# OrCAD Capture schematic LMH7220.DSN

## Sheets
1 Top_Block: size A
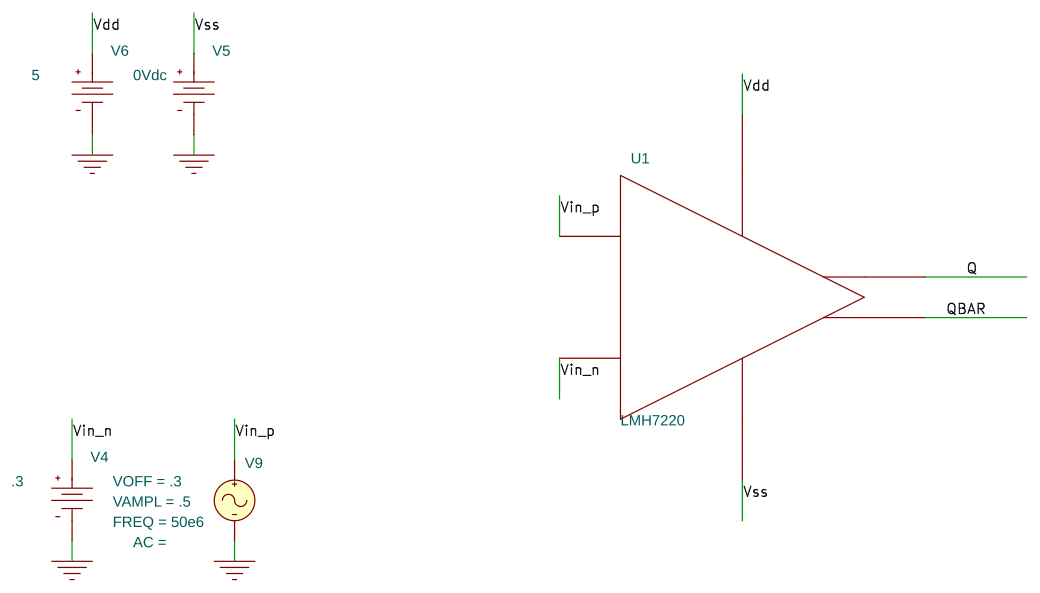
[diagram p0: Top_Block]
2 Top
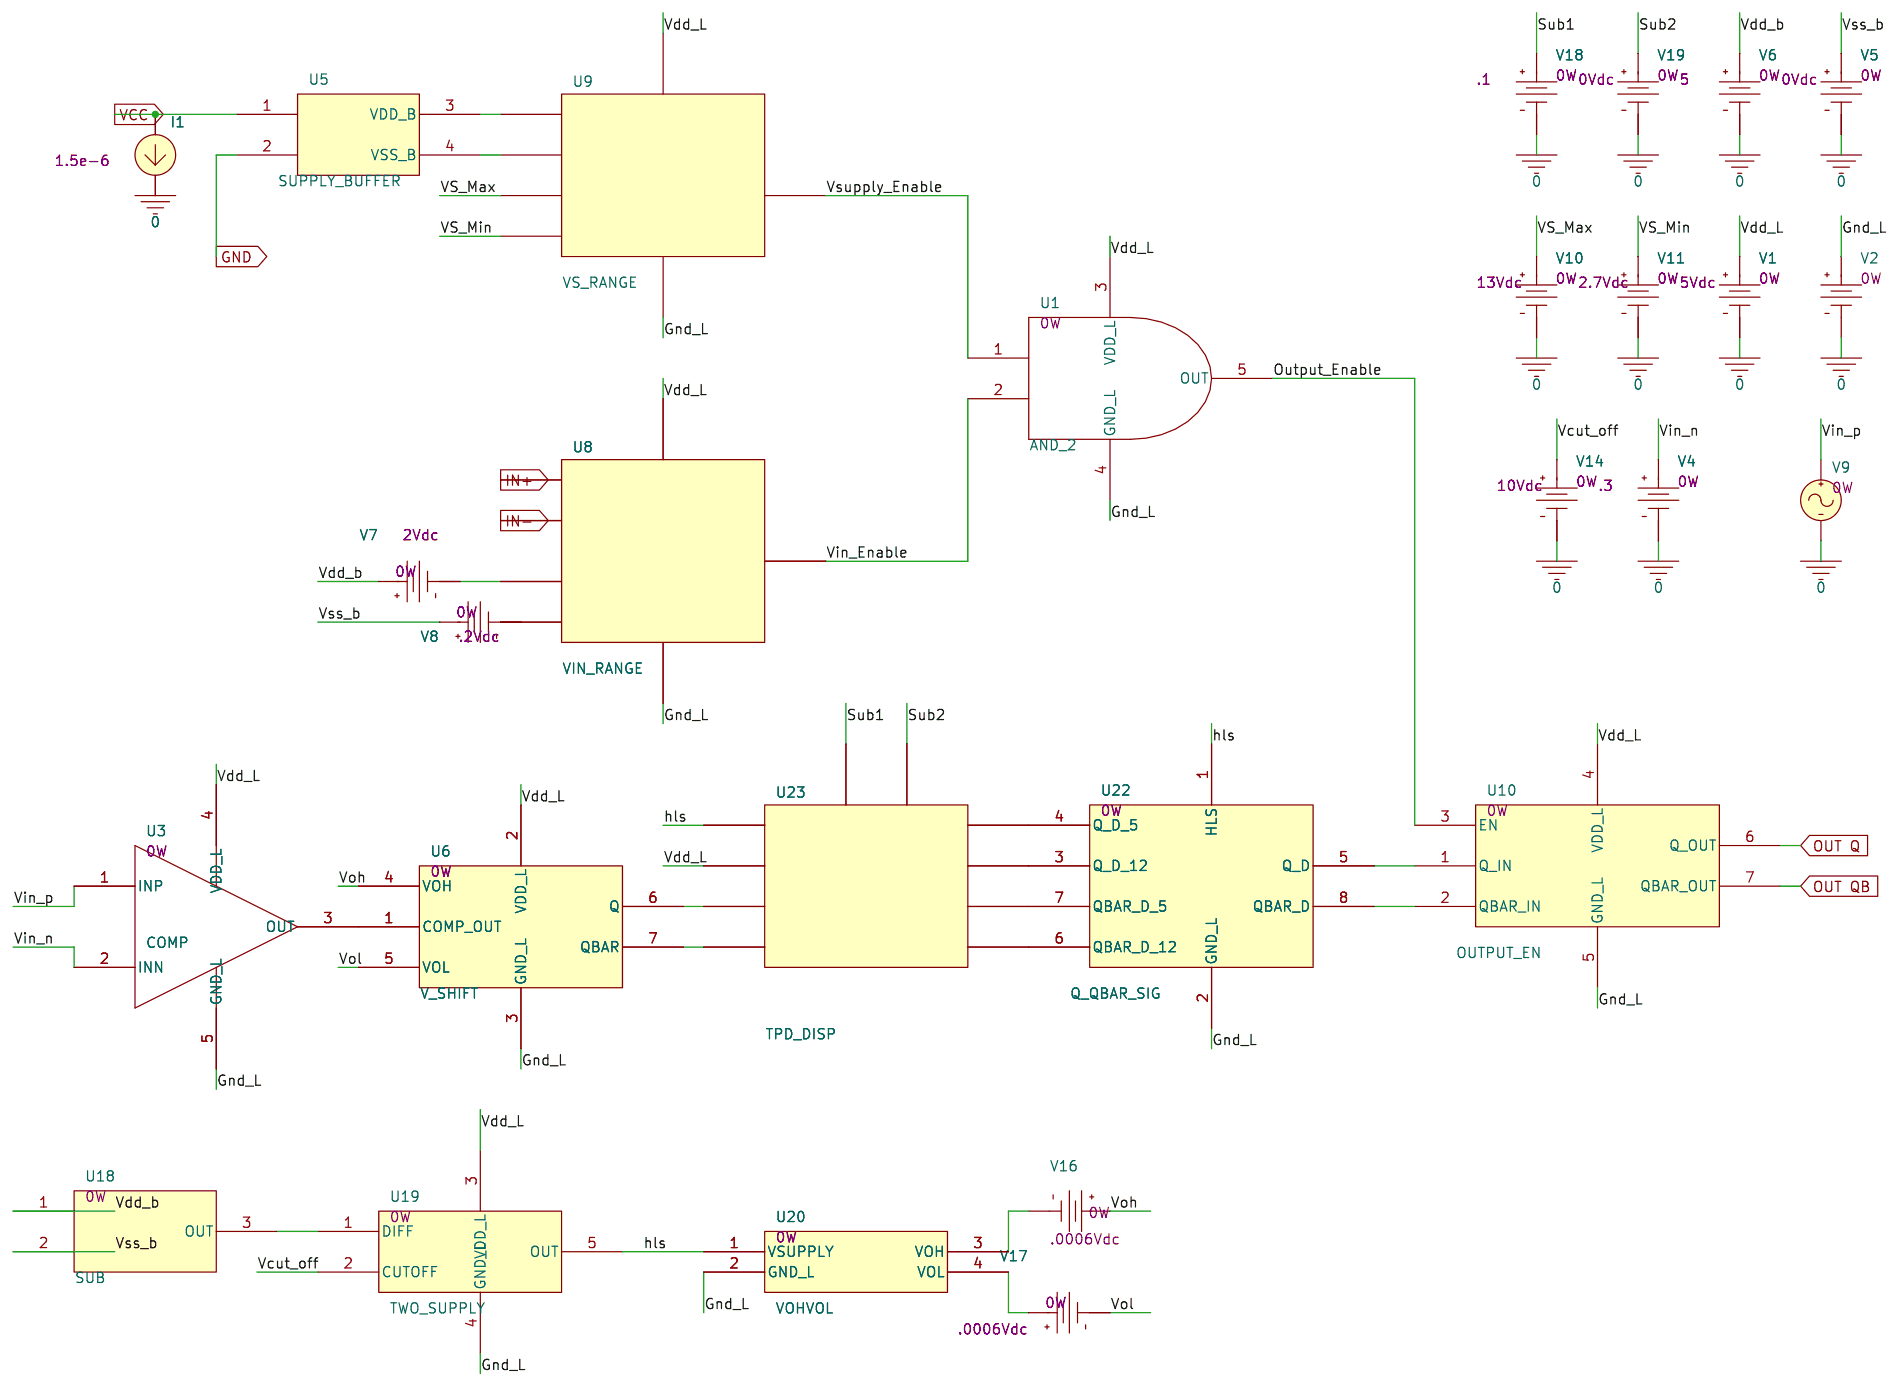
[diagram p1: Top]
3 PAGE2
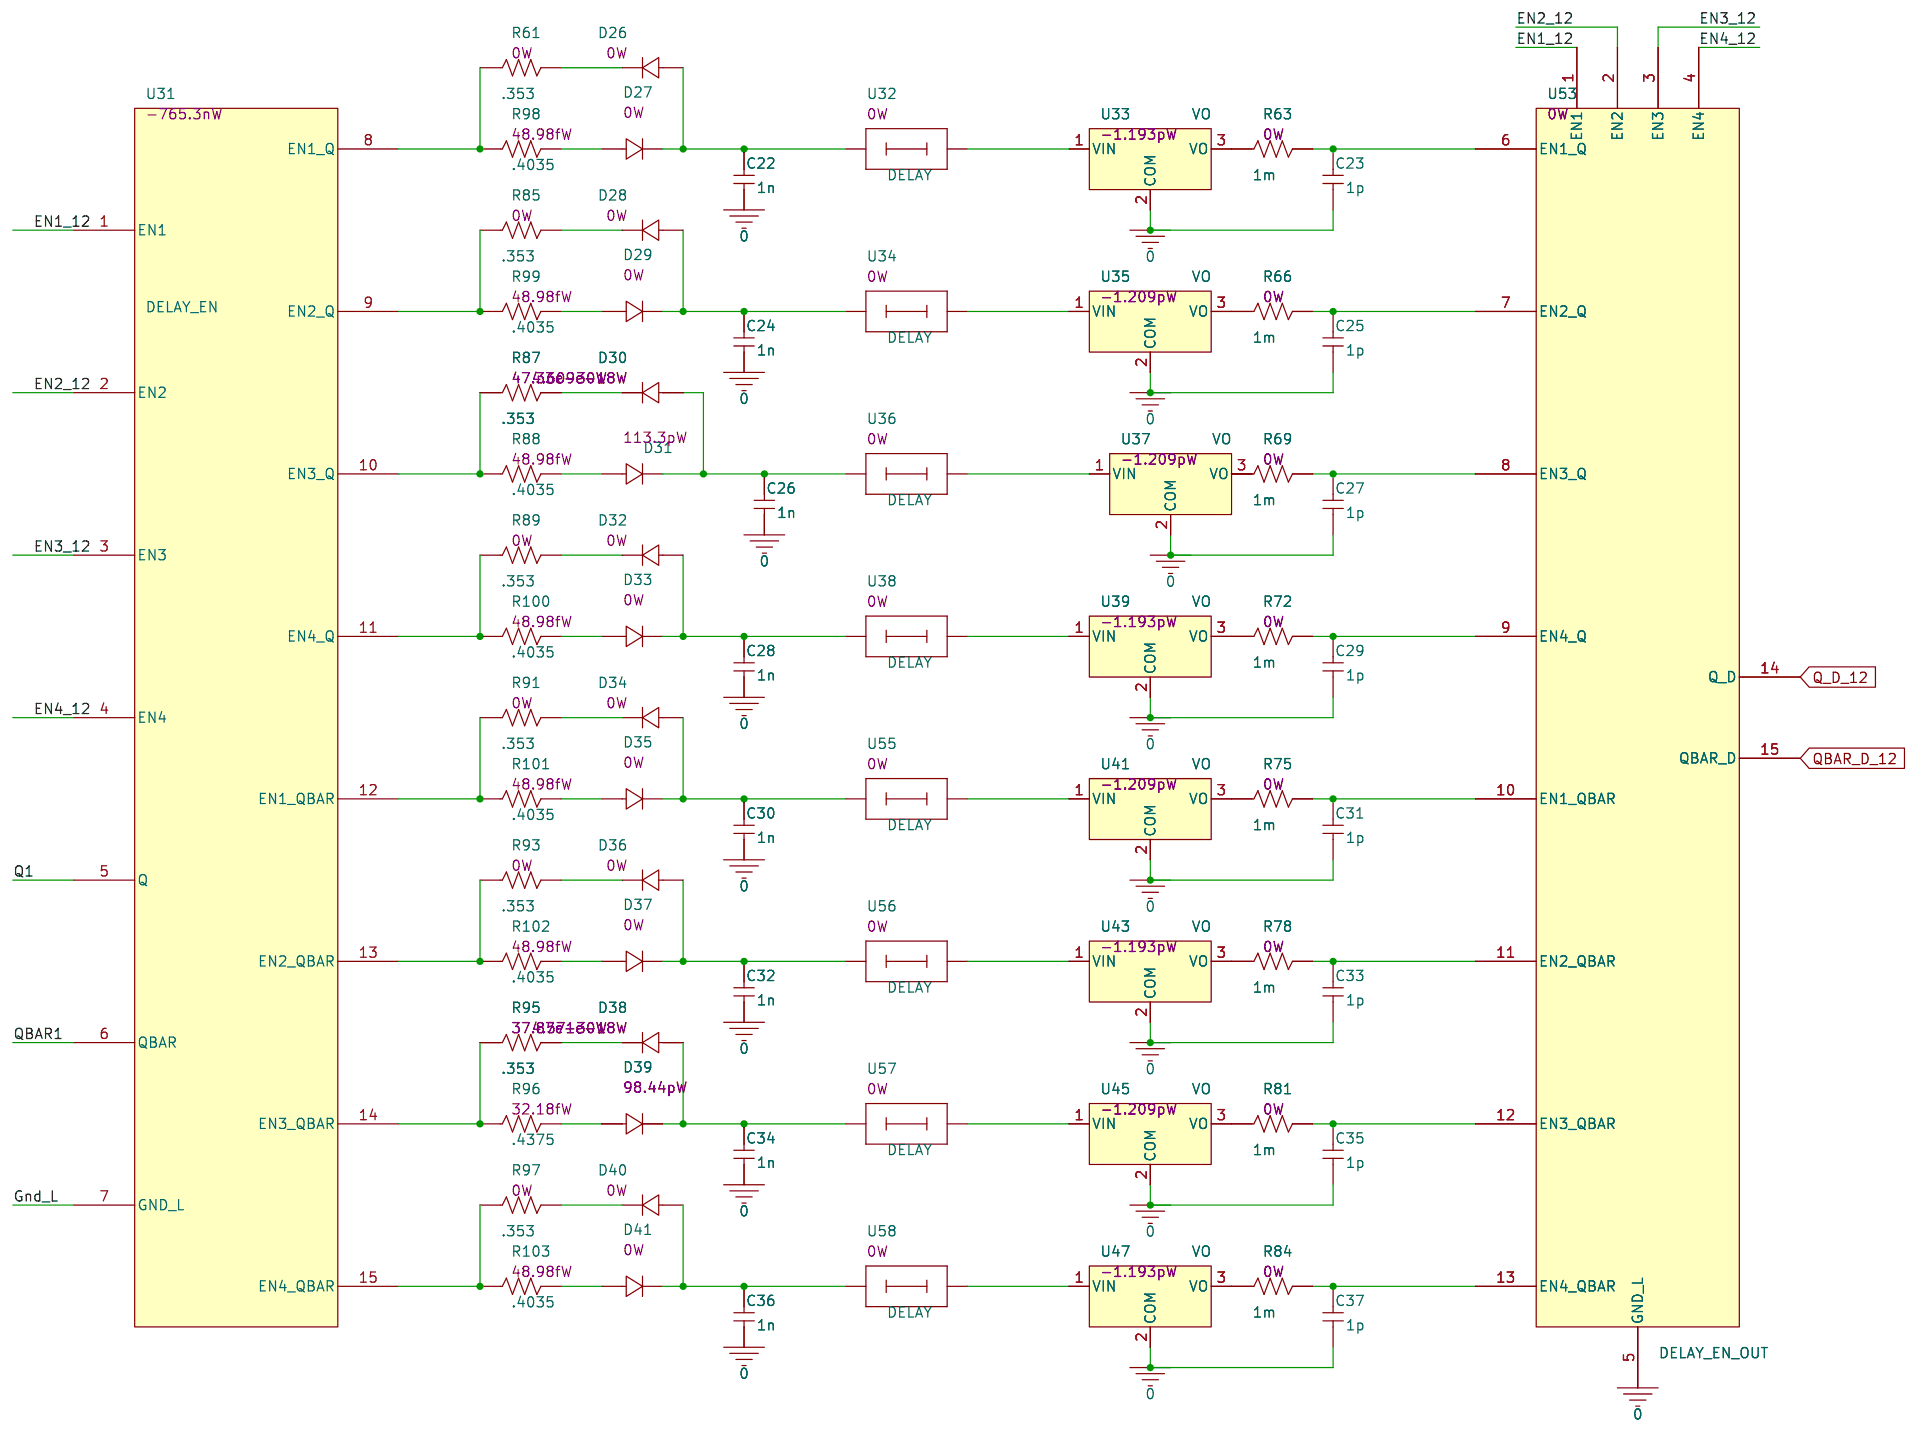
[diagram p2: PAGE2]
4 PAGE1
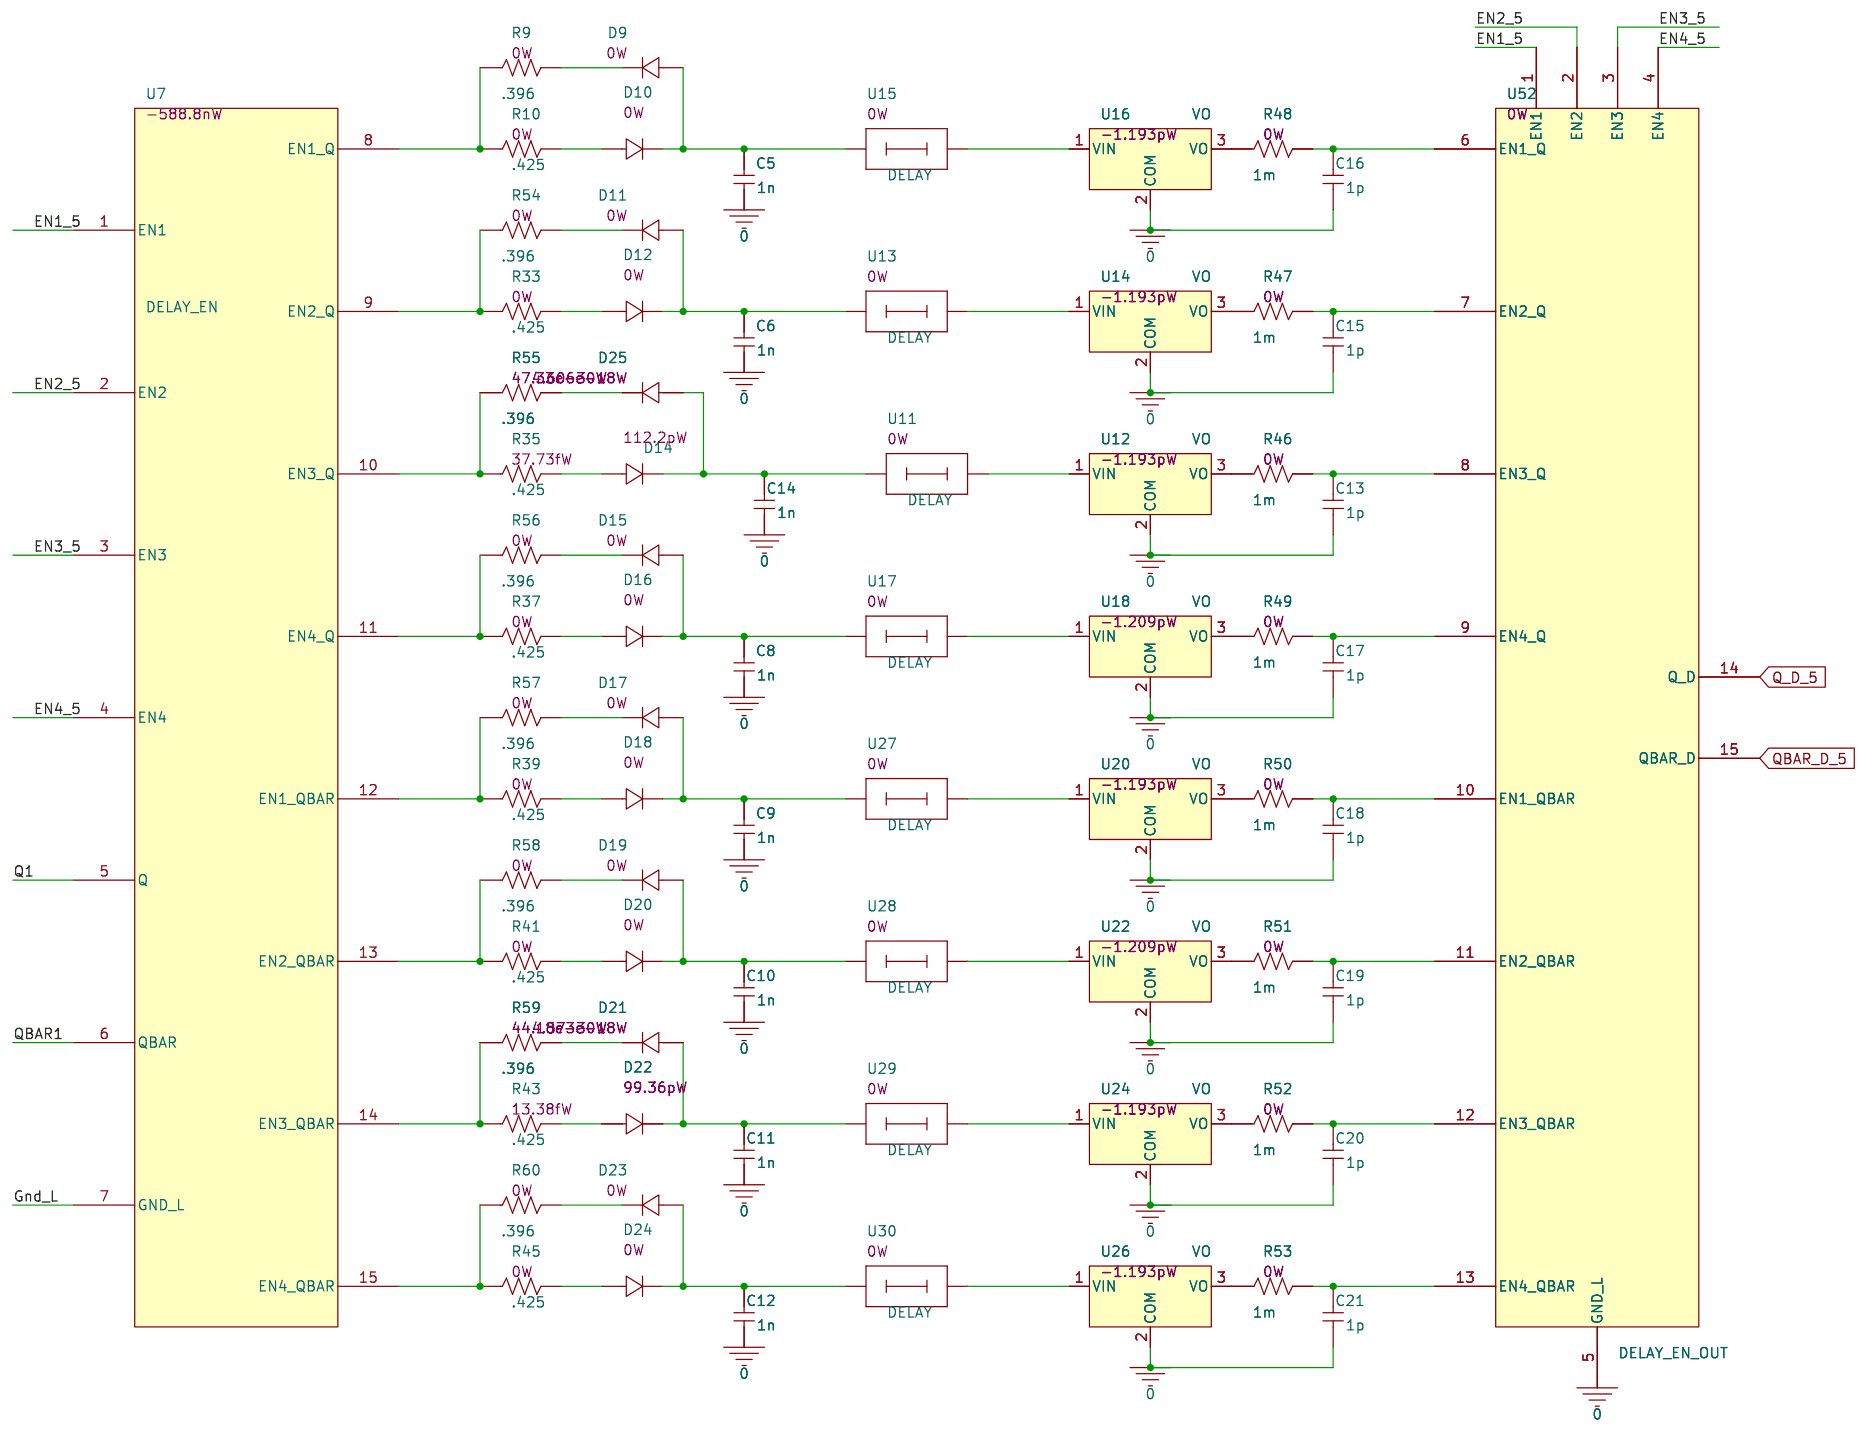
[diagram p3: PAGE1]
5 Tpd_Dispersion
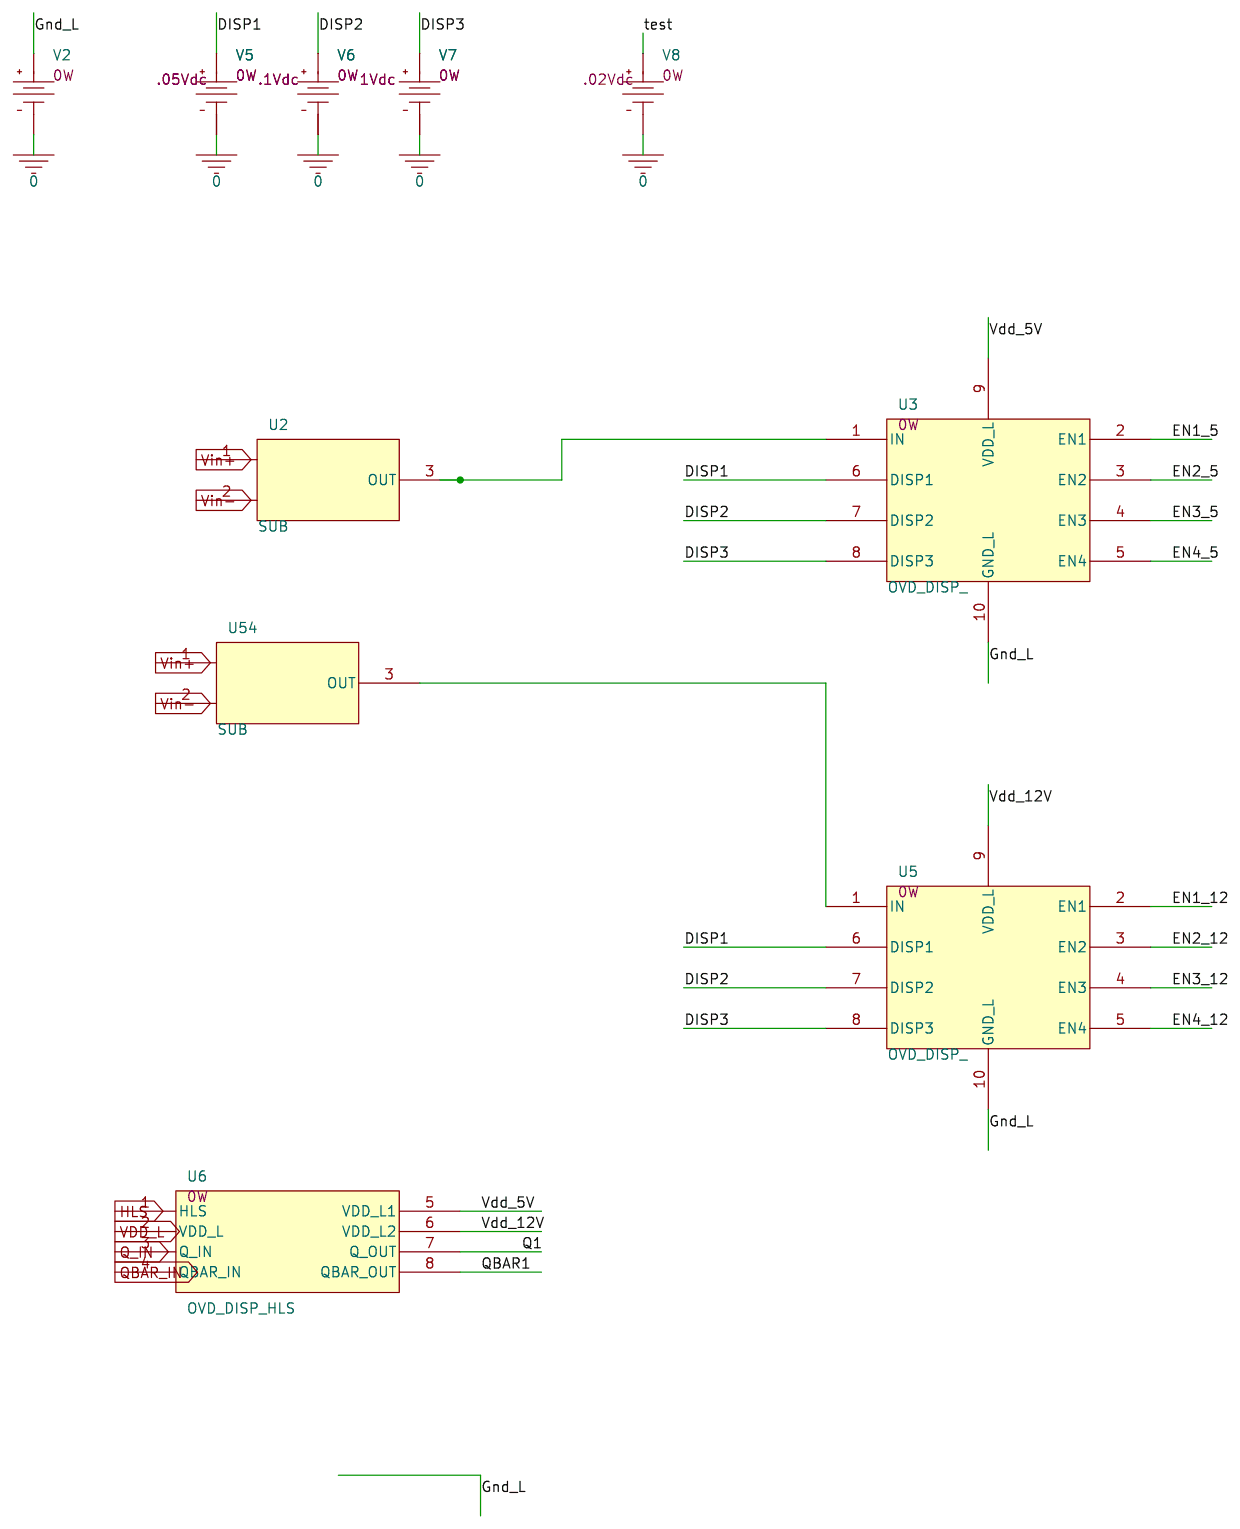
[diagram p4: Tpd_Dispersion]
6 Input_Range
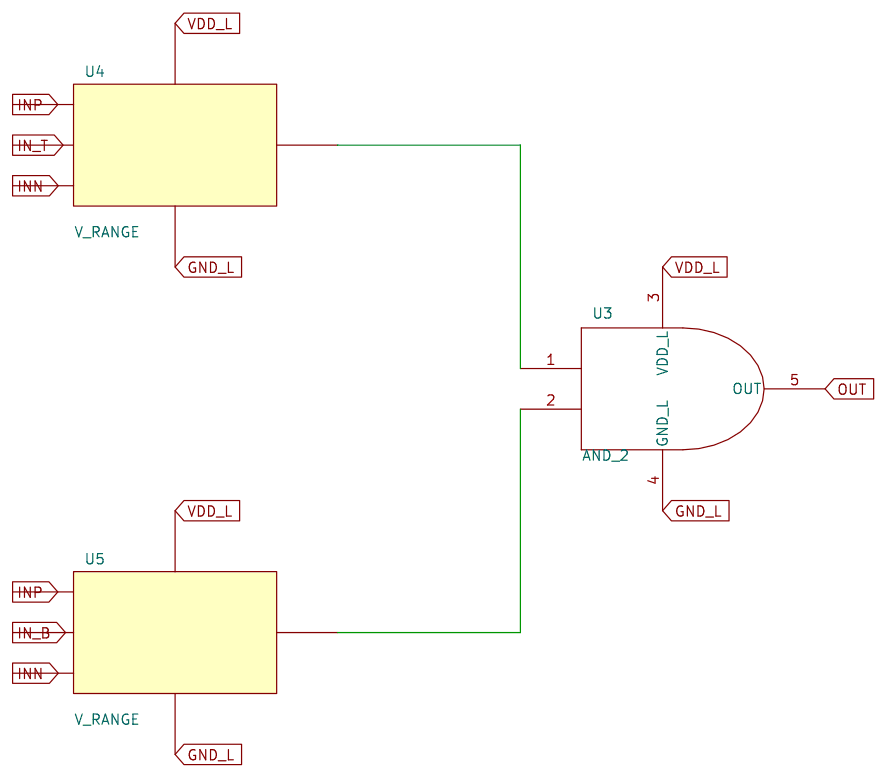
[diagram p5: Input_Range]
7 Voltage_Range
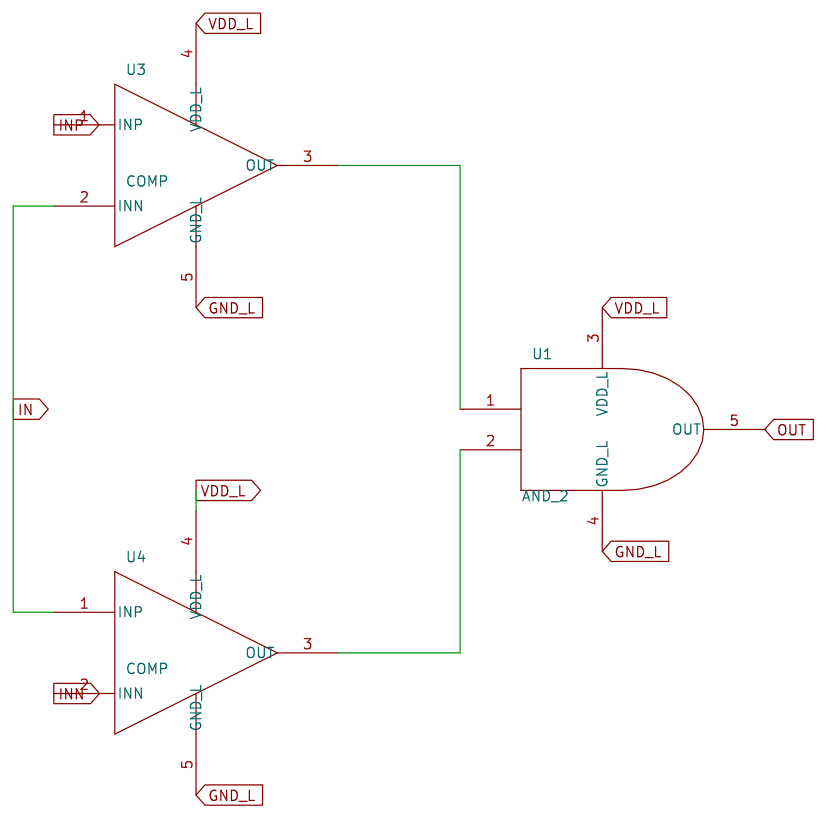
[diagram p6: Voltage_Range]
8 Voltage_Range (2)
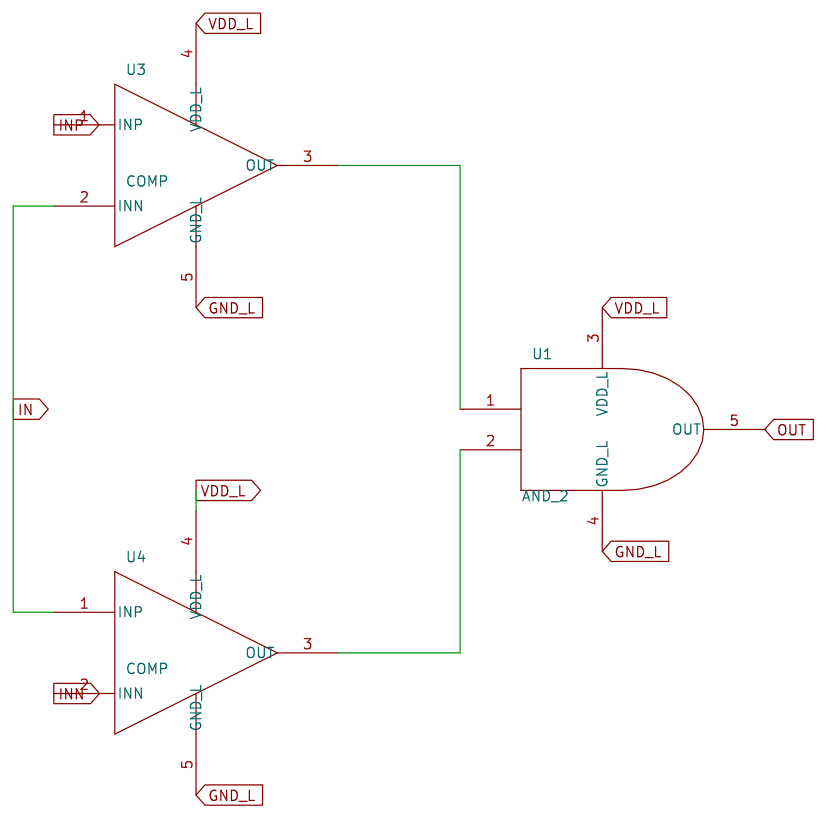
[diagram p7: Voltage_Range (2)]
9 Supply_Range
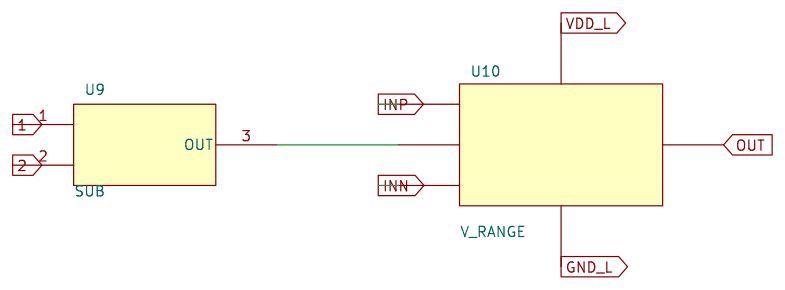
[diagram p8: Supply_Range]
10 Voltage_Range (3)
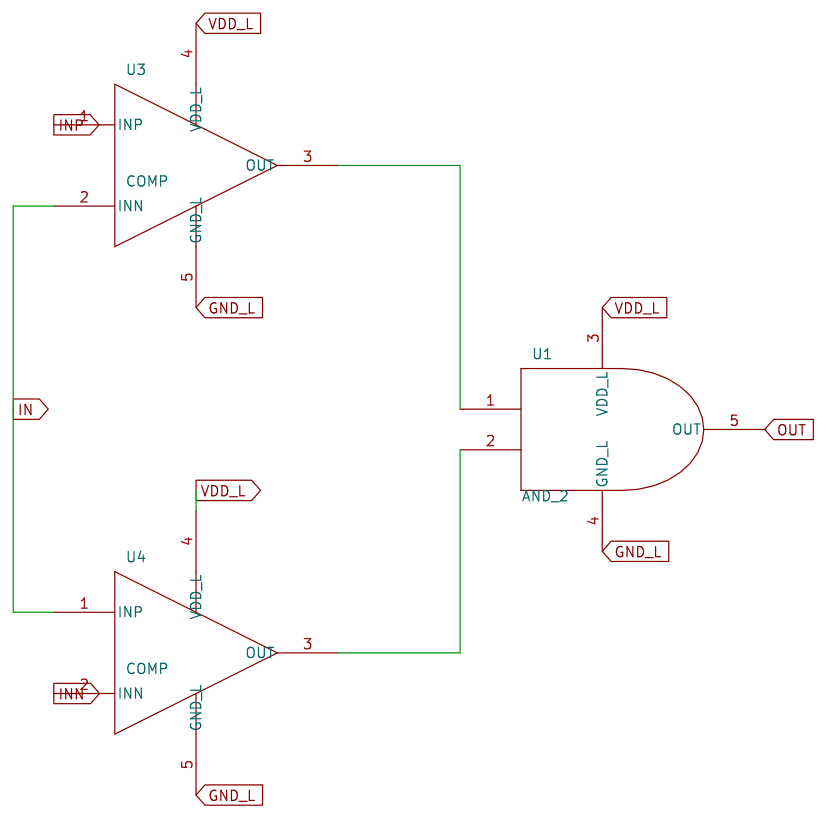
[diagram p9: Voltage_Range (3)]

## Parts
sheet PAGE1
C5  1n  [cap196]
C6  1n  [cap196]
C8  1n  [cap196]
C9  1n  [cap196]
C10  1n  [cap196]
C11  1n  [cap196]
C12  1n  [cap196]
C13  1p  [cap196]
C14  1n  [cap196]
C15  1p  [cap196]
C16  1p  [cap196]
C17  1p  [cap196]
C18  1p  [cap196]
C19  1p  [cap196]
C20  1p  [cap196]
C21  1p  [cap196]
D9  Dbreak
D10  Dbreak
D11  Dbreak
D12  Dbreak
D14  Dbreak
D15  Dbreak
D16  Dbreak
D17  Dbreak
D18  Dbreak
D19  Dbreak
D20  Dbreak
D21  Dbreak
D22  Dbreak
D23  Dbreak
D24  Dbreak
D25  Dbreak
R9  .396  [AXRC05]
R10  .425  [AXRC05]
R33  .425  [AXRC05]
R35  .425  [AXRC05]
R37  .425  [AXRC05]
R39  .425  [AXRC05]
R41  .425  [AXRC05]
R43  .425  [AXRC05]
R45  .425  [AXRC05]
R46  1m  [AXRC05]
R47  1m  [AXRC05]
R48  1m  [AXRC05]
R49  1m  [AXRC05]
R50  1m  [AXRC05]
R51  1m  [AXRC05]
R52  1m  [AXRC05]
R53  1m  [AXRC05]
R54  .396  [AXRC05]
R55  .396  [AXRC05]
R56  .396  [AXRC05]
R57  .396  [AXRC05]
R58  .396  [AXRC05]
R59  .396  [AXRC05]
R60  .396  [AXRC05]
U7  DELAY_EN
U11  DELAY
U12  VO
U13  DELAY
U14  VO
U15  DELAY
U16  VO
U17  DELAY
U24  VO
U26  VO
U27  DELAY
U28  DELAY
U29  DELAY
U30  DELAY
U52  DELAY_EN_OUT
sheet PAGE2
C22  1n  [cap196]
C23  1p  [cap196]
C24  1n  [cap196]
C25  1p  [cap196]
C26  1n  [cap196]
C27  1p  [cap196]
C28  1n  [cap196]
C29  1p  [cap196]
C30  1n  [cap196]
C31  1p  [cap196]
C32  1n  [cap196]
C33  1p  [cap196]
C34  1n  [cap196]
C35  1p  [cap196]
C36  1n  [cap196]
C37  1p  [cap196]
D26  Dbreak
D27  Dbreak
D28  Dbreak
D29  Dbreak
D30  Dbreak
D31  Dbreak
D32  Dbreak
D33  Dbreak
D34  Dbreak
D35  Dbreak
D36  Dbreak
D37  Dbreak
D38  Dbreak
D39  Dbreak
D40  Dbreak
D41  Dbreak
R61  .353  [AXRC05]
R63  1m  [AXRC05]
R66  1m  [AXRC05]
R69  1m  [AXRC05]
R72  1m  [AXRC05]
R75  1m  [AXRC05]
R78  1m  [AXRC05]
R81  1m  [AXRC05]
R84  1m  [AXRC05]
R85  .353  [AXRC05]
R87  .353  [AXRC05]
R88  .4035  [AXRC05]
R89  .353  [AXRC05]
R91  .353  [AXRC05]
R93  .353  [AXRC05]
R95  .353  [AXRC05]
R96  .4375  [AXRC05]
R97  .353  [AXRC05]
R98  .4035  [AXRC05]
R99  .4035  [AXRC05]
R100  .4035  [AXRC05]
R101  .4035  [AXRC05]
R102  .4035  [AXRC05]
R103  .4035  [AXRC05]
U31  DELAY_EN
U32  DELAY
U33  VO
U34  DELAY
U35  VO
U36  DELAY
U37  VO
U38  DELAY
U39  VO
U41  VO
U43  VO
U45  VO
U47  VO
U53  DELAY_EN_OUT
U55  DELAY
U56  DELAY
U57  DELAY
U58  DELAY
sheet Top
I1  IDC
U5  SUPPLY_BUFFER
U6  V_SHIFT
U8  VIN_RANGE
U9  VS_RANGE
U10  OUTPUT_EN
U18  SUB
U19  TWO_SUPPLY
U20  VOHVOL
U22  Q_QBAR_SIG
U23  TPD_DISP
V1  VDC
V2  VDC
V4  VDC
V5  VDC
V6  VDC
V7  VDC
V8  VDC
V9  VSIN
V10  VDC
V11  VDC
V14  VDC
V16  VDC
V17  VDC
V18  VDC
V19  VDC
sheet Tpd_Dispersion
U2  SUB
U54  SUB
sheet Voltage_Range (2)
U1  AND_2
U3  COMP
U4  COMP

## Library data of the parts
C5 C6 C8-C37 = C
D9-D12 D14-D41 = Dbreak
R9 R10 R33 R35 R37 R39 R41 R43 R45-R61 R63 R66 R69 R72 R75 R78 R81 R84 R85 R87-R89 R91 R93 R95-R103 = R
U7 U31 = DELAY_EN_6
U11 U29 = DELAY: DELAY: 2.61275n
U12 U14 U16 U24 U26 = VO: VOH: 1.38
U13 U15 U17 = DELAY: DELAY: 2n
U27 U28 U30 = DELAY: DELAY: 3n
U52 U53 = DELAY_EN_OUT_1
U32 U55 = DELAY: DELAY: 3.28615n
U33 U35 U37 U39 U41 U43 U45 U47 = VO: VOH: 1.39
U34 U56 = DELAY: DELAY: 2.70615n
U36 U57 = DELAY: DELAY: 2.42615n
U38 U58 = DELAY: DELAY: 1.96615n
I1 = IDC: DC: 1.5e-6
U5 = SUPPLY_BUFFER_0
U6 = V_SHIFT_0
U8 = VIN_RANGE
U9 = VS_RANGE
U10 = OUTPUT_EN_0
U2 U18 U54 = SUB_0
U19 = TWO_SUPPLY_0
U20 = VOHVOL
U22 = Q_QBAR_SIG_1
U23 = TPD_DISP_1
V1 = VDC: DC: 5Vdc
V2 = VDC
V4 = VDC: DC: .3
V5 V19 = VDC: DC: 0Vdc
V6 = VDC: DC: 5
V7 = VDC: DC: 2Vdc
V8 = VDC: DC: .2Vdc
V9 = VSIN: FREQ: 50e6; VAMPL: .5; VOFF: .3
V10 = VDC: DC: 13Vdc
V11 = VDC: DC: 2.7Vdc
V14 = VDC: DC: 10Vdc
V16 V17 = VDC: DC: .0006Vdc
V18 = VDC: DC: .1
U1 = AND_0
U3 U4 = COMP_0

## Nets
GND: U5.2
GND_L: U1.4(GND_L) U4.5(GND_L)
VCC: I1.1(+) U5.1
Vdd: U1.VCC V6.0(+)
VDD_L: U1.3(VDD_L) U3.3(VDD_L) U3.4(VDD_L) U4.(VDD_L) U4.4(VDD_L) U5.(VDD_L) U6.2(VDD_L) U10.(VDD_L)
Vin+: U2.1 U54.1
Vin-: U2.2 U54.2
Vin_n: U1.IN- V4.0(+)
Vin_p: U1.IN+ V9.1(+)
Vss: U1.GND V5.0(+)
0: C5.1 C6.1 C8.1 C9.1 C10.1 C11.1 C12.1 C13.1 C14.1 C15.1 C16.1 C17.1 C18.1 C19.1 C20.1 C21.1 C22.1 C23.1 C24.1 C25.1 C26.1 C27.1 C28.1 C29.1 C30.1 C31.1 C32.1 C33.1 C34.1 C35.1 C36.1 C37.1 I1.2(-) U12.2(COM) U14.2(COM) U16.2(COM) U18.2(COM) U20.2(COM) U22.2(COM) U24.2(COM) U26.2(COM) U33.2(COM) U35.2(COM) U37.2(COM) U39.2(COM) U41.2(COM) U43.2(COM) U45.2(COM) U47.2(COM) U52.5(GND_L) U53.5(GND_L) V1.1(-) V2.1(-) V4.1(-) V5.1(-) V6.1(-) V9.2(-) V10.1(-) V11.1(-) V14.1(-) V18.1(-) V19.1(-)
1: U9.1
2: U9.2
IN: U4.1(INP)
INN: U4.2(INN)
OUT: U1.5(OUT) U3.5(OUT)
OUT Q: U10.6(Q_OUT)
OUT QB: U10.7(QBAR_OUT)
Q: U1.OUT_Q
Q_D_5: U52.14(Q_D)
Q_D_12: U53.14(Q_D)
Q_IN: U6.3(Q_IN)
QBAR: U1.OUT_QB
QBAR_D_5: U52.15(QBAR_D)
QBAR_D_12: U53.15(QBAR_D)
QBAR_IN: U6.4(QBAR_IN)

Not connected (* = marked no-connect by the designer): C5 2; C6 2; C8 2; C9 2; C10 2; C11 2; C12 2; C13 2; C14 2; C15 2; C16 2; C17 2; C18 2; C19 2; C20 2; C21 2; C22 2; C23 2; C24 2; C25 2; C26 2; C27 2; C28 2; C29 2; C30 2; C31 2; C32 2; C33 2; C34 2; C35 2; C36 2; C37 2; D9 0(1) 1(2); D10 0(1) 1(2); D11 0(1) 1(2); D12 0(1) 1(2); D14 0(1) 1(2); D15 0(1) 1(2); D16 0(1) 1(2); D17 0(1) 1(2); D18 0(1) 1(2); D19 0(1) 1(2); D20 0(1) 1(2); D21 0(1) 1(2); D22 0(1) 1(2); D23 0(1) 1(2); D24 0(1) 1(2); D25 0(1) 1(2); D26 0(1) 1(2); D27 0(1) 1(2); D28 0(1) 1(2); D29 0(1) 1(2); D30 0(1) 1(2); D31 0(1) 1(2); D32 0(1) 1(2); D33 0(1) 1(2); D34 0(1) 1(2); D35 0(1) 1(2); D36 0(1) 1(2); D37 0(1) 1(2); D38 0(1) 1(2); D39 0(1) 1(2); D40 0(1) 1(2); D41 0(1) 1(2); R9 1 2; R10 1 2; R33 1 2; R35 1 2; R37 1 2; R39 1 2; R41 1 2; R43 1 2; R45 1 2; R46 1 2; R47 1 2; R48 1 2; R49 1 2; R50 1 2; R51 1 2; R52 1 2; R53 1 2; R54 1 2; R55 1 2; R56 1 2; R57 1 2; R58 1 2; R59 1 2; R60 1 2; R61 1 2; R63 1 2; R66 1 2; R69 1 2; R72 1 2; R75 1 2; R78 1 2; R81 1 2; R84 1 2; R85 1 2; R87 1 2; R88 1 2; R89 1 2; R91 1 2; R93 1 2; R95 1 2; R96 1 2; R97 1 2; R98 1 2; R99 1 2; R100 1 2; R101 1 2; R102 1 2; R103 1 2; U1 1 2; U2 3(OUT); U3 1 2 6(DISP1) 7(DISP2) 8(DISP3) 9(VDD_L) 10(GND_L); U4 3(OUT); U5 3(VDD_B) 4(VSS_B) 5(EN4) 6(DISP1) 7(DISP2) 8(DISP3) 9(VDD_L) 10(GND_L); U6 1(COMP_OUT) 5(VDD_L1) 6(Q) 7(QBAR) 8(QBAR_OUT); U7 1(EN1) 2(EN2) 3(EN3) 4(EN4) 5(Q) 6(QBAR) 7(GND_L) 8(EN1_Q) 9(EN2_Q) 10(EN3_Q) 11(EN4_Q) 12(EN1_QBAR) 13(EN2_QBAR) 14(EN3_QBAR) 15(EN4_QBAR); U8 (INP); U9 (2) 3(OUT); U10 1(Q_IN) 2(QBAR_IN) 3(EN) 4(VDD_L) 5(GND_L); U11 1(A) 2(B); U12 1(VIN) 3(VO); U13 1(A) 2(B); U14 1(VIN) 3(VO); U15 1(A) 2(B); U16 1(VIN) 3(VO); U17 1(A) 2(B); U18 1(VIN) 3(VO); U19 1(DIFF) 2(CUTOFF) 3(VDD_L) 4(GND_L) 5(OUT); U20 1(VIN) 3(VOH) 4(VOL); U22 1(VIN) 3(VO) 4(Q_D_5) 5(Q_D) 6(QBAR_D_12) 7(QBAR_D_5) 8(QBAR_D); U23 (Q_IN); U24 1(VIN) 3(VO); U26 1(VIN) 3(VO); U27 1(A) 2(B); U28 1(A) 2(B); U29 1(A) 2(B); U30 1(A) 2(B); U31 1(EN1) 2(EN2) 3(EN3) 4(EN4) 5(Q) 6(QBAR) 7(GND_L) 8(EN1_Q) 9(EN2_Q) 10(EN3_Q) 11(EN4_Q) 12(EN1_QBAR) 13(EN2_QBAR) 14(EN3_QBAR) 15(EN4_QBAR); U32 1(A) 2(B); U33 1(VIN) 3(VO); U34 1(A) 2(B); U35 1(VIN) 3(VO); U36 1(A) 2(B); U37 1(VIN) 3(VO); U38 1(A) 2(B); U39 1(VIN) 3(VO); U41 1(VIN) 3(VO); U43 1(VIN) 3(VO); U45 1(VIN) 3(VO); U47 1(VIN) 3(VO); U52 1(EN1) 2(EN2) 3(EN3) 4(EN4) 6(EN1_Q) 7(EN2_Q) 8(EN3_Q) 9(EN4_Q) 10(EN1_QBAR) 11(EN2_QBAR) 12(EN3_QBAR) 13(EN4_QBAR); U53 1(EN1) 2(EN2) 3(EN3) 4(EN4) 6(EN1_Q) 7(EN2_Q) 8(EN3_Q) 9(EN4_Q) 10(EN1_QBAR) 11(EN2_QBAR) 12(EN3_QBAR) 13(EN4_QBAR); U54 3(OUT); U55 1(A) 2(B); U56 1(A) 2(B); U57 1(A) 2(B); U58 1(A) 2(B); V1 0(+); V2 0(+); V7 0(+) 1(-); V8 0(+) 1(-); V10 0(+); V11 0(+); V14 0(+); V16 0(+) 1(-); V17 0(+) 1(-); V18 0(+); V19 0(+)
